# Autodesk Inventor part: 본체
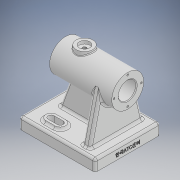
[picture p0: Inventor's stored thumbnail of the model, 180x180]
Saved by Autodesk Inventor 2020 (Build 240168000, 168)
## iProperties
Created: 2021-11
Part Number: 본체
Material: 일반
Document SubType Name: Modeling
Designer: user
Density: 1 g/cm^3
Appearance: 기본값
Author: user
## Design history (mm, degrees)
sketch "스케치1"
  geometry: L1 (0, 0)-(82, 0); L2 (0, 14.5)-(0, 21); L3 (0, 21)-(82, 21); L4 (82, 21)-(82, 11.5); L5 (82, 11.5)-(62, 11.5); L6 (62, 11.5)-(62, 14.5); L7 (62, 14.5)-(0, 14.5); 2 further points
  constraints: 14 end point, 5 perpendicular, 2 midpoint, 2 vertical alignment, 1 horizontal, 1 vertical
  dimensions: "d0" = 82 distance of L1.start L1.end; "d1" = 42 diameter of L3 L1; "d2" = 29 diameter of L7 L1; "d3" = 23 diameter of L5 L1; "d4" = 62 distance of L2.start L6.end
revolve "회전1" sketch "스케치1" stored, may be unused: angle "d5" = 90 deg
node "작업 평면1"
sketch "스케치2"
  geometry: C1 r 11 at (-25, 0); 1 further point
  constraints: 1 centre point, 1 horizontal alignment
  dimensions: "d7" = 22 diameter of C1; "d8" = 25 distance of point (0, 0) C1.centre
extrude "돌출1" join sketch "스케치2" stored distance "d9" = 10; taper "d10" = 0 deg
sketch "스케치3"
  geometry: C1 r 11 at (0, 0) reference; C2 r 7 at (0, 0); 1 further point
  constraints: 1 centre point, 1 coincident
  dimensions: "d11" = 14 diameter of C2
extrude "돌출2" cut sketch "스케치3" distance "d12" = 4; taper "d13" = 0 deg
sketch "스케치4"
  geometry: C1 r 7 at (0, 0) reference; 2 further points
  constraints: 1 coincident
hole "구멍1" sketch "스케치4" at (0, 0) diameter "d14" = 4.917; stored, may be unused: countersink angle "d18" = 90 deg, drill point angle "d20" = 0 deg; dims "d15" = 12, "d16" = 4, "d17" = 2, "d19" = 17.1
node "작업 평면2"
sketch "스케치5"
  geometry: L1 (-82, 21)-(-82, -21) reference; L2 (-82, 0)-(-82, -43); L3 (-82, -43)-(18, -43); L4 (18, -43)-(18, 43); L5 (18, 43)-(-82, 43); L6 (-82, 43)-(-82, 0); 3 further points
  constraints: 10 end point, 2 perpendicular, 1 collinear, 1 midpoint, 1 point on line
  dimensions: "d22" = 43 distance of L2.start L2.end; "d23" = 100 distance of L2.end L3.end; "d24" = 86 distance of L3.end L4.end; "d25" = 100 distance of L4.end L5.end
extrude "돌출3" join sketch "스케치5" distance "d26" = 15; taper "d27" = 0 deg
node "작업 평면3"
sketch "스케치8"
  geometry: L1 (-57, -43)-(-72, -43) reference; L2 (-72, -43)-(-72, 43) reference; L3 (-72, 43)-(-57, 43) reference; L4 (-57, 43)-(-57, -43) reference; L5 (4.814, 20.441)-(-57, 35); L6 (-57, 43)-(-57, -43) reference; L7 (-57, -35)-(4.814, -20.441); C1 r 14.5 at (0, 0) reference; C2 r 21 at (0, 0) reference; C3 r 11.5 at (0, 0) reference; A1 r 21 centre (0, 0) between (4.814, 20.441) and (4.814, -20.441) reference; 5 further points
  constraints: 4 end point, 2 point on circle, 2 point on line, 2 tangent
  dimensions: "d31" = 8 distance from line of L3 L5.end; "d32" = 8 distance from line of L1 L7.start
extrude "돌출4" join sketch "스케치8" stored distance "d33" = 10; taper "d34" = 0 deg
sketch "스케치11"
  geometry: L1 (10.103, -21)-(-3, -57); L2 (14, 21)-(14, 24) reference; L3 (14, 24)-(18, 24) reference; L4 (18, 24)-(18, 20) reference; L5 (18, 20)-(22.541, 20) reference; L6 (22.541, 20)-(22.541, 14.5) reference; L7 (22.541, 14.5)-(0, 14.5) reference; L8 (0, 14.5)-(0, 21) reference; L9 (0, 21)-(14, 21) reference; L10 (36, 24)-(36, 21) reference; L11 (36, 21)-(82, 21) reference; L12 (82, 21)-(82, 11.5) reference; L13 (82, 11.5)-(62, 11.5) reference; L14 (62, 11.5)-(62, 14.5) reference; L15 (62, 14.5)-(27.459, 14.5) reference; L16 (27.459, 14.5)-(27.459, 20) reference; L17 (27.459, 20)-(32, 20) reference; L18 (32, 20)-(32, 24) reference; L19 (32, 24)-(36, 24) reference; L20 (0, -14.5)-(62, -14.5) reference; L21 (62, -14.5)-(62, -11.5) reference; L22 (62, -11.5)-(82, -11.5) reference; L23 (82, -11.5)-(82, -21) reference; L24 (82, -21)-(67, -21) reference; L25 (67, -21)-(67, -57) reference; L26 (67, -57)-(82, -57) reference; L27 (82, -57)-(82, -72) reference; L28 (82, -72)-(-18, -72) reference; L29 (-18, -72)-(-18, -57) reference; L30 (-18, -57)-(57, -57) reference; L31 (57, -57)-(57, -21) reference; L32 (57, -21)-(0, -21) reference; L33 (0, -21)-(0, -14.5) reference; 1 further point
  constraints: 2 end point, 2 point on line
  dimensions: "d35" = 15 distance from line of L29 L1.end; "d37" = 70 deg angle of L30 L1
  node "절단 모서리 투영3"
sketch "스케치12"
  geometry: L1 (82, 43)-(-18, 43) reference; L2 (8, 27)-(20, 27); L3 (8, 20)-(20, 20); L4 (20, 34)-(8, 34); L5 (-18, 43)-(-18, -43) reference; A1 r 7 centre (8, 27) between (8, 34) and (8, 20); A2 r 7 centre (20, 27) between (20, 20) and (20, 34); 2 further points
  constraints: 8 end point, 4 point on circle, 4 tangent, 2 centre point, 1 horizontal, 1 midpoint, 1 parallel
  dimensions: "d41" = 12 distance of L2.start L2.end; "d42" = 26 distance from line of L5 L2.start; "d43" = 27 vertical distance of point (0, 0) point (14, 27); "d44" = 14 distance between parallel lines of L3 L4
extrude "돌출6" join sketch "스케치12" distance "d45" = 3; taper "d46" = 0 deg
sketch "스케치15"
  geometry: L1 (8, 27)-(20, 27); L2 (8, 23)-(20, 23); L3 (20, 31)-(8, 31); L4 (8, -27)-(20, -27); L5 (8, -31)-(20, -31); L6 (20, -23)-(8, -23); A1 r 7 centre (8, 27) between (8, 34) and (8, 20) reference; A2 r 7 centre (20, 27) between (20, 20) and (20, 34) reference; A3 r 4 centre (8, 27) between (8, 31) and (8, 23); A4 r 4 centre (20, 27) between (20, 23) and (20, 31); A5 r 7 centre (8, -27) between (8, -20) and (8, -34) reference; A6 r 7 centre (20, -27) between (20, -34) and (20, -20) reference; A7 r 4 centre (8, -27) between (8, -23) and (8, -31); A8 r 4 centre (20, -27) between (20, -31) and (20, -23); 3 further points
  constraints: 16 end point, 8 point on circle, 8 tangent, 4 centre point, 2 horizontal, 2 midpoint, 2 parallel
  dimensions: "d50" = 8 diameter of A4; "d51" = 8 diameter of A8
extrude "돌출7" cut sketch "스케치15" distance "d52" = 33.75; taper "d53" = 0 deg
sketch "스케치16"
  geometry: 2 further points
  constraints: 1 vertical alignment
  dimensions: "d54" = 18 distance of point (0, 0) point (0, 18)
hole "구멍2" sketch "스케치16" at (0, 18) diameter "d55" = 2.459; stored, may be unused: countersink angle "d59" = 90 deg, drill point angle "d61" = 0 deg; dims "d56" = 8, "d57" = 4, "d58" = 2, "d60" = 10
sketch "스케치18"
  geometry: 2 further points
  constraints: 1 vertical alignment
  dimensions: "d65" = 18 distance of point (0, 0) point (0, 18)
feature "리브1" dims "d66" = 1, "d67" = 10, "d68" = 0, "d69" = 0, "d70" = 1, "d71" = 1
hole "구멍3" sketch "스케치18" diameter "d72" = 2.459; stored, may be unused: countersink angle "d76" = 90 deg, drill point angle "d78" = 0 deg; dims "d73" = 8, "d74" = 4, "d75" = 2, "d77" = 10
fillet "모깎기1" dims "d82" = 3
fillet "모깎기2" dims "d83" = 3
fillet "모깎기3" dims "d84" = 3
chamfer "모따기1" distance "d85" = 1; stored, may be unused: second distance "d86" = 2, angle "d87" = 45 deg
fillet "모깎기4" dims "d88" = 3
fillet "모깎기5" dims "d89" = 3
fillet "모깎기6" dims "d90" = 1
sketch "스케치19"
  geometry: L1 (0, 0)-(80, 0) reference; 2 further points
  constraints: 1 vertical alignment, 1 other
  dimensions: "d91" = 6 distance from line of L1 point (40, 6)
feature "엠보싱1" sketch "스케치19" dims "d0" = 82, "d1" = 42, "d2" = 29, "d3" = 23, "d4" = 62, "d13" = 0, "d92" = 0.5, "d93" = 0
node "솔리드1"
pattern_linear "직사각형 패턴1" dims "d49" = 54
pattern_circular "원형 패턴1" dims angle "d63" = 360 deg
pattern_circular "원형 패턴2" dims angle "d80" = 360 deg
node "절단 모서리 투영2"
feature "A9D066F2-1C7D-4E18-AEED-F7BC21143FA4" dims "d14" = 4.917, "d15" = 12, "d16" = 4, "d17" = 2, "d18" = 90 deg, "d19" = 17.1, "d20" = 0
other parameters: "d6" = 24, "d21" = -72, "d28" = 62
